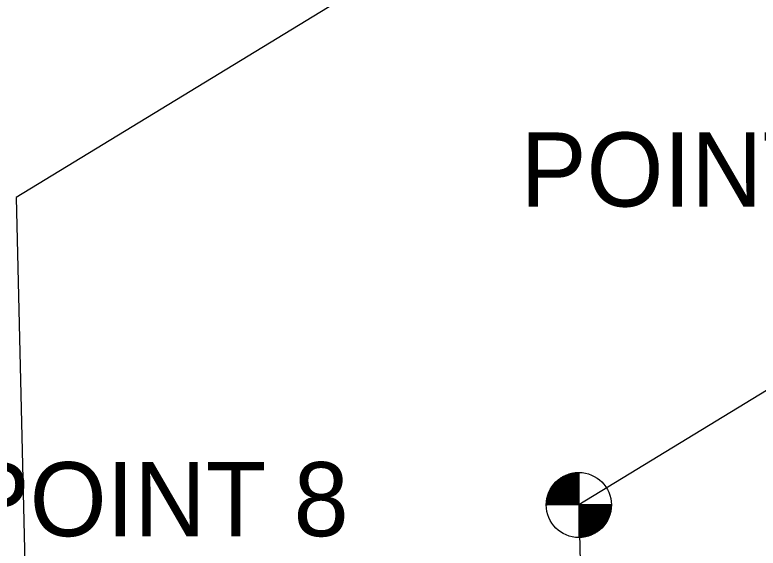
# Model space of a CAD drawing. Extents: x 2091245 to 2092168, y 863656 to 864307.
# Drawn here: x 2091641.82 to 2091681.99, y 863946.01 to 863974.81 of the extents above; entities that cross this region are included whole.
import ezdxf

# ---------------------------------------------------------------- set-up
doc = ezdxf.new("R2010")
doc.units = 0
for name, color, linetype in [('Exist Hydrographic Top of Bank', 7, 'Continuous'), ('Prop Boundary Buffer Zone 1', 7, 'Continuous'), ('Scratch_Level_6', 7, 'Continuous')]:
    doc.layers.add(name, color=color, linetype=linetype)

msp = doc.modelspace()

# ---------------------------------------------------------------- linework, layer by layer
at = {"layer": 'Exist Hydrographic Top of Bank'}
msp.add_lwpolyline([(2091672.3, 863948.34), (2091672.795, 863927.55), (2091675.886, 863922.062), (2091703.915, 863935.563), (2091732.111, 863967.919), (2091742.84, 863995.86), (2091771.423, 864017.904), (2091796.939, 864035.122), (2091802.35, 864043.97), (2091798.347, 864050.35), (2091774.513, 864034.247), (2091751.1, 864019.64), (2091722.53, 863989.28), (2091717.91, 863987.56), (2091701.99, 863966.43)], close=True, dxfattribs=at)
at = {"layer": 'Prop Boundary Buffer Zone 1'}
msp.add_lwpolyline([(2091641.896, 863964.945), (2091642.981, 863919.351), (2091663.555, 863882.824), (2091722.485, 863911.209), (2091758.215, 863952.211), (2091767.828, 863977.246), (2091788.992, 863993.568), (2091819.128, 864013.904), (2091837.639, 864044.171), (2091807.267, 864092.583), (2091758.17, 864059.411), (2091731.919, 864043.033), (2091705.49, 864014.948), (2091699.226, 864012.616), (2091681.482, 863989.064)], close=True, dxfattribs=at)
at = {"layer": 'Scratch_Level_6'}
for p, q in [((2091670.543, 863948.374), (2091672.266, 863950.097)), ((2091670.544, 863948.41), (2091672.23, 863950.096)), ((2091670.544, 863948.34), (2091672.3, 863950.096)), ((2091670.546, 863948.447), (2091672.193, 863950.094)), ((2091670.548, 863948.485), (2091672.154, 863950.091)), ((2091670.552, 863948.525), (2091672.116, 863950.088)), ((2091670.557, 863948.565), (2091672.075, 863950.083)), ((2091670.563, 863948.606), (2091672.034, 863950.077)), ((2091670.57, 863948.648), (2091671.992, 863950.07)), ((2091670.578, 863948.692), (2091671.948, 863950.062)), ((2091670.58, 863948.34), (2091672.3, 863950.06)), ((2091670.588, 863948.737), (2091671.903, 863950.052)), ((2091670.599, 863948.784), (2091671.856, 863950.04)), ((2091670.613, 863948.833), (2091671.807, 863950.027)), ((2091670.615, 863948.34), (2091672.3, 863950.025)), ((2091670.629, 863948.884), (2091671.756, 863950.011)), ((2091670.647, 863948.938), (2091671.702, 863949.993)), ((2091670.65, 863948.34), (2091672.3, 863949.99)), ((2091670.669, 863948.995), (2091671.645, 863949.971)), ((2091670.686, 863948.34), (2091672.3, 863949.954)), ((2091670.695, 863949.056), (2091671.583, 863949.945)), ((2091670.721, 863948.34), (2091672.3, 863949.919)), ((2091670.726, 863949.123), (2091671.517, 863949.913)), ((2091670.756, 863948.34), (2091672.3, 863949.884)), ((2091670.766, 863949.198), (2091671.442, 863949.874)), ((2091671.41, 863949.856), (2091672.3, 863948.965)), ((2091671.432, 863949.868), (2091672.3, 863949.001)), ((2091671.455, 863949.881), (2091672.3, 863949.036)), ((2091671.478, 863949.893), (2091672.3, 863949.072)), ((2091671.501, 863949.906), (2091672.3, 863949.107)), ((2091671.525, 863949.917), (2091672.3, 863949.142)), ((2091671.549, 863949.929), (2091672.3, 863949.178)), ((2091671.573, 863949.94), (2091672.3, 863949.213)), ((2091671.597, 863949.951), (2091672.3, 863949.248)), ((2091671.622, 863949.962), (2091672.3, 863949.284)), ((2091671.647, 863949.972), (2091672.3, 863949.319)), ((2091671.673, 863949.982), (2091672.3, 863949.354)), ((2091671.698, 863949.991), (2091672.3, 863949.39)), ((2091671.724, 863950.001), (2091672.3, 863949.425)), ((2091671.751, 863950.01), (2091672.3, 863949.46)), ((2091671.778, 863950.018), (2091672.3, 863949.496)), ((2091671.805, 863950.026), (2091672.3, 863949.531)), ((2091671.832, 863950.034), (2091672.3, 863949.567)), ((2091671.86, 863950.042), (2091672.3, 863949.602)), ((2091671.888, 863950.049), (2091672.3, 863949.637)), ((2091671.917, 863950.055), (2091672.3, 863949.673)), ((2091671.946, 863950.062), (2091672.3, 863949.708)), ((2091671.976, 863950.067), (2091672.3, 863949.743)), ((2091672.006, 863950.073), (2091672.3, 863949.779)), ((2091672.036, 863950.078), (2091672.3, 863949.814)), ((2091672.067, 863950.082), (2091672.3, 863949.849)), ((2091672.099, 863950.086), (2091672.3, 863949.885)), ((2091672.131, 863950.089), (2091672.3, 863949.92)), ((2091672.163, 863950.092), (2091672.3, 863949.955)), ((2091672.196, 863950.095), (2091672.3, 863949.991)), ((2091672.23, 863950.096), (2091672.3, 863950.026)), ((2091672.264, 863950.097), (2091672.3, 863950.062)), ((2091672.299, 863950.098), (2091672.3, 863950.097)), ((2091672.3, 863950.098), (2091672.3, 863946.582)), ((2091670.792, 863948.34), (2091672.3, 863949.848)), ((2091670.819, 863949.286), (2091671.354, 863949.821)), ((2091670.827, 863948.34), (2091672.3, 863949.813)), ((2091670.863, 863948.34), (2091672.3, 863949.777)), ((2091670.898, 863948.34), (2091672.3, 863949.742)), ((2091670.901, 863949.403), (2091671.237, 863949.739)), ((2091670.933, 863948.34), (2091672.3, 863949.707)), ((2091670.951, 863949.466), (2091672.077, 863948.34)), ((2091670.967, 863949.485), (2091672.112, 863948.34)), ((2091670.969, 863948.34), (2091672.3, 863949.671)), ((2091670.983, 863949.504), (2091672.148, 863948.34)), ((2091671, 863949.523), (2091672.183, 863948.34)), ((2091671.004, 863948.34), (2091672.3, 863949.636)), ((2091671.017, 863949.541), (2091672.218, 863948.34)), ((2091671.034, 863949.559), (2091672.254, 863948.34)), ((2091671.039, 863948.34), (2091672.3, 863949.601)), ((2091671.052, 863949.577), (2091672.289, 863948.34)), ((2091671.069, 863949.595), (2091672.3, 863948.364)), ((2091671.075, 863948.34), (2091672.3, 863949.565)), ((2091671.088, 863949.612), (2091672.3, 863948.4)), ((2091671.106, 863949.629), (2091672.3, 863948.435)), ((2091671.11, 863948.34), (2091672.3, 863949.53)), ((2091671.124, 863949.646), (2091672.3, 863948.471)), ((2091671.143, 863949.663), (2091672.3, 863948.506)), ((2091671.145, 863948.34), (2091672.3, 863949.495)), ((2091671.162, 863949.679), (2091672.3, 863948.541)), ((2091671.181, 863949.695), (2091672.3, 863948.577)), ((2091671.181, 863948.34), (2091672.3, 863949.459)), ((2091671.201, 863949.711), (2091672.3, 863948.612)), ((2091671.22, 863949.727), (2091672.3, 863948.647)), ((2091671.24, 863949.742), (2091672.3, 863948.683)), ((2091671.261, 863949.757), (2091672.3, 863948.718)), ((2091671.281, 863949.772), (2091672.3, 863948.753)), ((2091671.302, 863949.787), (2091672.3, 863948.789)), ((2091671.323, 863949.801), (2091672.3, 863948.824)), ((2091671.344, 863949.815), (2091672.3, 863948.859)), ((2091671.366, 863949.829), (2091672.3, 863948.895)), ((2091671.388, 863949.842), (2091672.3, 863948.93)), ((2091670.693, 863949.052), (2091671.405, 863948.34)), ((2091670.704, 863949.076), (2091671.441, 863948.34)), ((2091670.715, 863949.1), (2091671.476, 863948.34)), ((2091670.727, 863949.124), (2091671.511, 863948.34)), ((2091670.739, 863949.148), (2091671.547, 863948.34)), ((2091670.751, 863949.171), (2091671.582, 863948.34)), ((2091670.764, 863949.194), (2091671.617, 863948.34)), ((2091670.776, 863949.216), (2091671.653, 863948.34)), ((2091670.79, 863949.239), (2091671.688, 863948.34)), ((2091670.803, 863949.261), (2091671.723, 863948.34)), ((2091670.816, 863949.282), (2091671.759, 863948.34)), ((2091670.83, 863949.304), (2091671.794, 863948.34)), ((2091670.844, 863949.325), (2091671.829, 863948.34)), ((2091670.859, 863949.346), (2091671.865, 863948.34)), ((2091670.873, 863949.367), (2091671.9, 863948.34)), ((2091670.888, 863949.387), (2091671.936, 863948.34)), ((2091670.904, 863949.407), (2091671.971, 863948.34)), ((2091670.919, 863949.427), (2091672.006, 863948.34)), ((2091670.935, 863949.447), (2091672.042, 863948.34)), ((2091671.216, 863948.34), (2091672.3, 863949.424)), ((2091671.251, 863948.34), (2091672.3, 863949.389)), ((2091671.287, 863948.34), (2091672.3, 863949.353)), ((2091671.322, 863948.34), (2091672.3, 863949.318)), ((2091671.358, 863948.34), (2091672.3, 863949.282)), ((2091671.393, 863948.34), (2091672.3, 863949.247)), ((2091671.428, 863948.34), (2091672.3, 863949.212)), ((2091671.464, 863948.34), (2091672.3, 863949.176)), ((2091671.499, 863948.34), (2091672.3, 863949.141)), ((2091671.534, 863948.34), (2091672.3, 863949.106)), ((2091671.57, 863948.34), (2091672.3, 863949.07)), ((2091670.575, 863948.676), (2091670.91, 863948.34)), ((2091670.581, 863948.705), (2091670.946, 863948.34)), ((2091670.587, 863948.734), (2091670.981, 863948.34)), ((2091670.594, 863948.762), (2091671.016, 863948.34)), ((2091670.601, 863948.791), (2091671.052, 863948.34)), ((2091670.609, 863948.818), (2091671.087, 863948.34)), ((2091670.617, 863948.846), (2091671.122, 863948.34)), ((2091670.625, 863948.873), (2091671.158, 863948.34)), ((2091670.634, 863948.899), (2091671.193, 863948.34)), ((2091670.643, 863948.926), (2091671.228, 863948.34)), ((2091670.652, 863948.952), (2091671.264, 863948.34)), ((2091670.662, 863948.977), (2091671.299, 863948.34)), ((2091670.672, 863949.003), (2091671.334, 863948.34)), ((2091670.682, 863949.027), (2091671.37, 863948.34)), ((2091671.605, 863948.34), (2091672.3, 863949.035)), ((2091671.64, 863948.34), (2091672.3, 863949)), ((2091671.676, 863948.34), (2091672.3, 863948.964)), ((2091671.711, 863948.34), (2091672.3, 863948.929)), ((2091671.746, 863948.34), (2091672.3, 863948.894)), ((2091671.782, 863948.34), (2091672.3, 863948.858)), ((2091671.817, 863948.34), (2091672.3, 863948.823)), ((2091671.853, 863948.34), (2091672.3, 863948.787)), ((2091671.888, 863948.34), (2091672.3, 863948.752)), ((2091671.923, 863948.34), (2091672.3, 863948.717)), ((2091671.959, 863948.34), (2091672.3, 863948.681)), ((2091670.542, 863948.354), (2091670.557, 863948.34)), ((2091674.058, 863948.34), (2091670.542, 863948.34)), ((2091670.543, 863948.389), (2091670.592, 863948.34)), ((2091670.544, 863948.423), (2091670.627, 863948.34)), ((2091670.546, 863948.456), (2091670.663, 863948.34)), ((2091670.549, 863948.489), (2091670.698, 863948.34)), ((2091670.552, 863948.522), (2091670.733, 863948.34)), ((2091670.555, 863948.554), (2091670.769, 863948.34)), ((2091670.56, 863948.585), (2091670.804, 863948.34)), ((2091670.564, 863948.615), (2091670.84, 863948.34)), ((2091670.569, 863948.646), (2091670.875, 863948.34)), ((2091671.994, 863948.34), (2091672.3, 863948.646)), ((2091672.029, 863948.34), (2091672.3, 863948.611)), ((2091672.065, 863948.34), (2091672.3, 863948.575)), ((2091672.1, 863948.34), (2091672.3, 863948.54)), ((2091672.135, 863948.34), (2091672.3, 863948.505)), ((2091672.171, 863948.34), (2091672.3, 863948.469)), ((2091672.206, 863948.34), (2091672.3, 863948.434)), ((2091672.241, 863948.34), (2091672.3, 863948.399)), ((2091672.277, 863948.34), (2091672.3, 863948.363)), ((2091672.3, 863948.305), (2091672.335, 863948.34)), ((2091672.3, 863948.27), (2091672.37, 863948.34)), ((2091672.3, 863948.235), (2091672.405, 863948.34)), ((2091672.3, 863948.199), (2091672.441, 863948.34)), ((2091672.3, 863948.164), (2091672.476, 863948.34)), ((2091672.3, 863948.129), (2091672.511, 863948.34)), ((2091672.3, 863948.093), (2091672.547, 863948.34)), ((2091672.3, 863948.058), (2091672.582, 863948.34)), ((2091672.3, 863948.023), (2091672.617, 863948.34)), ((2091672.3, 863947.987), (2091672.653, 863948.34)), ((2091672.3, 863947.952), (2091672.688, 863948.34)), ((2091672.3, 863947.917), (2091672.723, 863948.34)), ((2091672.3, 863947.881), (2091672.759, 863948.34)), ((2091672.3, 863947.846), (2091672.794, 863948.34)), ((2091672.3, 863947.811), (2091672.829, 863948.34)), ((2091672.3, 863947.775), (2091672.865, 863948.34)), ((2091672.3, 863947.74), (2091672.9, 863948.34)), ((2091672.3, 863947.704), (2091672.936, 863948.34)), ((2091672.3, 863947.669), (2091672.971, 863948.34)), ((2091672.3, 863947.634), (2091673.006, 863948.34)), ((2091672.3, 863947.598), (2091673.042, 863948.34)), ((2091672.3, 863947.563), (2091673.077, 863948.34)), ((2091672.3, 863947.528), (2091673.112, 863948.34)), ((2091672.3, 863947.492), (2091673.148, 863948.34)), ((2091672.3, 863947.457), (2091673.183, 863948.34)), ((2091672.3, 863947.422), (2091673.218, 863948.34)), ((2091672.3, 863947.386), (2091673.254, 863948.34)), ((2091672.3, 863947.351), (2091673.289, 863948.34)), ((2091672.3, 863947.316), (2091673.324, 863948.34)), ((2091672.3, 863947.28), (2091673.36, 863948.34)), ((2091672.3, 863947.245), (2091673.395, 863948.34)), ((2091672.3, 863947.209), (2091673.431, 863948.34)), ((2091672.3, 863947.174), (2091673.466, 863948.34)), ((2091672.3, 863947.139), (2091673.501, 863948.34)), ((2091672.3, 863947.103), (2091673.537, 863948.34)), ((2091672.3, 863947.068), (2091673.572, 863948.34)), ((2091672.3, 863947.033), (2091673.607, 863948.34)), ((2091672.3, 863946.997), (2091673.643, 863948.34)), ((2091672.3, 863946.962), (2091673.678, 863948.34)), ((2091672.3, 863946.927), (2091673.713, 863948.34)), ((2091672.3, 863946.891), (2091673.749, 863948.34)), ((2091672.3, 863946.856), (2091673.784, 863948.34)), ((2091672.3, 863946.821), (2091673.819, 863948.34)), ((2091672.3, 863946.785), (2091673.855, 863948.34)), ((2091672.3, 863946.75), (2091673.89, 863948.34)), ((2091672.3, 863946.714), (2091673.926, 863948.34)), ((2091672.3, 863946.679), (2091673.961, 863948.34)), ((2091672.3, 863946.644), (2091673.996, 863948.34)), ((2091672.3, 863946.608), (2091674.032, 863948.34)), ((2091672.3, 863948.335), (2091673.54, 863947.095)), ((2091672.3, 863948.3), (2091673.522, 863947.077)), ((2091672.3, 863948.264), (2091673.504, 863947.06)), ((2091672.309, 863946.582), (2091674.058, 863948.331)), ((2091672.33, 863948.34), (2091673.558, 863947.112)), ((2091672.345, 863946.583), (2091674.057, 863948.295)), ((2091672.366, 863948.34), (2091673.575, 863947.13)), ((2091672.382, 863946.584), (2091674.056, 863948.258)), ((2091672.401, 863948.34), (2091673.592, 863947.149)), ((2091672.436, 863948.34), (2091673.609, 863947.167)), ((2091672.472, 863948.34), (2091673.626, 863947.186)), ((2091672.507, 863948.34), (2091673.642, 863947.205)), ((2091672.542, 863948.34), (2091673.658, 863947.224)), ((2091672.578, 863948.34), (2091673.674, 863947.244)), ((2091672.613, 863948.34), (2091673.69, 863947.264)), ((2091672.649, 863948.34), (2091673.705, 863947.284)), ((2091672.684, 863948.34), (2091673.72, 863947.304)), ((2091672.719, 863948.34), (2091673.735, 863947.325)), ((2091672.755, 863948.34), (2091673.749, 863947.345)), ((2091672.79, 863948.34), (2091673.763, 863947.367)), ((2091672.825, 863948.34), (2091673.777, 863947.388)), ((2091672.861, 863948.34), (2091673.791, 863947.409)), ((2091672.896, 863948.34), (2091673.804, 863947.432)), ((2091672.931, 863948.34), (2091673.818, 863947.454)), ((2091672.967, 863948.34), (2091673.831, 863947.476)), ((2091673.002, 863948.34), (2091673.843, 863947.499)), ((2091673.037, 863948.34), (2091673.856, 863947.522)), ((2091673.073, 863948.34), (2091673.868, 863947.545)), ((2091673.108, 863948.34), (2091673.879, 863947.569)), ((2091673.143, 863948.34), (2091673.891, 863947.593)), ((2091673.179, 863948.34), (2091673.902, 863947.617)), ((2091673.214, 863948.34), (2091673.913, 863947.641)), ((2091673.25, 863948.34), (2091673.923, 863947.666)), ((2091673.285, 863948.34), (2091673.933, 863947.691)), ((2091673.32, 863948.34), (2091673.943, 863947.717)), ((2091673.356, 863948.34), (2091673.953, 863947.743)), ((2091673.391, 863948.34), (2091673.962, 863947.769)), ((2091673.426, 863948.34), (2091673.971, 863947.795)), ((2091673.462, 863948.34), (2091673.98, 863947.822)), ((2091673.497, 863948.34), (2091673.988, 863947.849)), ((2091673.532, 863948.34), (2091673.995, 863947.877)), ((2091673.568, 863948.34), (2091674.003, 863947.905)), ((2091673.603, 863948.34), (2091674.01, 863947.933)), ((2091673.638, 863948.34), (2091674.016, 863947.962)), ((2091673.674, 863948.34), (2091674.023, 863947.991)), ((2091673.709, 863948.34), (2091674.028, 863948.021)), ((2091673.745, 863948.34), (2091674.034, 863948.051)), ((2091673.78, 863948.34), (2091674.038, 863948.081)), ((2091673.815, 863948.34), (2091674.043, 863948.112)), ((2091673.851, 863948.34), (2091674.047, 863948.144)), ((2091673.886, 863948.34), (2091674.05, 863948.176)), ((2091673.921, 863948.34), (2091674.053, 863948.209)), ((2091673.957, 863948.34), (2091674.055, 863948.242)), ((2091673.992, 863948.34), (2091674.056, 863948.276)), ((2091674.027, 863948.34), (2091674.057, 863948.31)), ((2091672.3, 863948.229), (2091673.486, 863947.043)), ((2091672.3, 863948.194), (2091673.467, 863947.026)), ((2091672.3, 863948.158), (2091673.449, 863947.01)), ((2091672.3, 863948.123), (2091673.429, 863946.993)), ((2091672.3, 863948.087), (2091673.41, 863946.977)), ((2091672.3, 863948.052), (2091673.391, 863946.962)), ((2091672.3, 863948.017), (2091673.371, 863946.946)), ((2091672.3, 863947.981), (2091673.351, 863946.931)), ((2091672.3, 863947.946), (2091673.33, 863946.916)), ((2091672.3, 863947.911), (2091673.309, 863946.901)), ((2091672.3, 863947.875), (2091673.289, 863946.887)), ((2091672.419, 863946.586), (2091674.053, 863948.22)), ((2091672.458, 863946.59), (2091674.051, 863948.182)), ((2091672.497, 863946.594), (2091674.046, 863948.143)), ((2091672.537, 863946.598), (2091674.041, 863948.102)), ((2091672.579, 863946.605), (2091674.035, 863948.061)), ((2091672.622, 863946.612), (2091674.028, 863948.018)), ((2091672.666, 863946.621), (2091674.019, 863947.974)), ((2091672.712, 863946.631), (2091674.009, 863947.928)), ((2091672.759, 863946.643), (2091673.996, 863947.881)), ((2091672.3, 863947.84), (2091673.267, 863946.873)), ((2091672.3, 863947.805), (2091673.246, 863946.859)), ((2091672.3, 863947.769), (2091673.224, 863946.845)), ((2091672.3, 863947.734), (2091673.202, 863946.832)), ((2091672.3, 863947.699), (2091673.18, 863946.819)), ((2091672.3, 863947.663), (2091673.157, 863946.806)), ((2091672.3, 863947.628), (2091673.135, 863946.793)), ((2091672.3, 863947.592), (2091673.112, 863946.781)), ((2091672.3, 863947.557), (2091673.088, 863946.769)), ((2091672.3, 863947.522), (2091673.064, 863946.757)), ((2091672.3, 863947.486), (2091673.04, 863946.746)), ((2091672.3, 863947.451), (2091673.016, 863946.735)), ((2091672.809, 863946.658), (2091673.982, 863947.831)), ((2091672.861, 863946.674), (2091673.966, 863947.779)), ((2091672.916, 863946.694), (2091673.946, 863947.725)), ((2091672.974, 863946.717), (2091673.923, 863947.666)), ((2091673.037, 863946.744), (2091673.896, 863947.603)), ((2091673.106, 863946.778), (2091673.862, 863947.534)), ((2091673.185, 863946.821), (2091673.819, 863947.456)), ((2091672.3, 863947.416), (2091672.992, 863946.724)), ((2091672.3, 863947.38), (2091672.967, 863946.714)), ((2091672.3, 863947.345), (2091672.941, 863946.704)), ((2091672.3, 863947.31), (2091672.916, 863946.694)), ((2091672.3, 863947.274), (2091672.89, 863946.684)), ((2091672.3, 863947.239), (2091672.864, 863946.675)), ((2091672.3, 863947.204), (2091672.837, 863946.666)), ((2091672.3, 863947.168), (2091672.81, 863946.658)), ((2091672.3, 863947.133), (2091672.783, 863946.65)), ((2091672.3, 863947.098), (2091672.755, 863946.642)), ((2091672.3, 863947.062), (2091672.727, 863946.635)), ((2091673.279, 863946.881), (2091673.76, 863947.361)), ((2091673.418, 863946.984), (2091673.657, 863947.223)), ((2091672.3, 863947.027), (2091672.699, 863946.628)), ((2091672.3, 863946.991), (2091672.67, 863946.622)), ((2091672.3, 863946.956), (2091672.64, 863946.616)), ((2091672.3, 863946.921), (2091672.611, 863946.61)), ((2091672.3, 863946.885), (2091672.58, 863946.605)), ((2091672.3, 863946.85), (2091672.55, 863946.6)), ((2091672.3, 863946.815), (2091672.519, 863946.596)), ((2091672.3, 863946.779), (2091672.487, 863946.592)), ((2091672.3, 863946.744), (2091672.455, 863946.589)), ((2091672.3, 863946.709), (2091672.422, 863946.587)), ((2091672.3, 863946.673), (2091672.389, 863946.585)), ((2091672.3, 863946.638), (2091672.355, 863946.583)), ((2091672.3, 863946.603), (2091672.32, 863946.583))]:
    msp.add_line(p, q, dxfattribs=at)
msp.add_circle((2091672.3, 863948.34), 1.758, dxfattribs=at)

# ---------------------------------------------------------------- texts
for s, p in [('POINT 7', (2091669.151, 863964.461)), ('POINT 8', (2091639.056, 863946.655))]:
    msp.add_text(s, height=4, dxfattribs=at).set_placement(p)

doc.saveas('drawing.dxf')
